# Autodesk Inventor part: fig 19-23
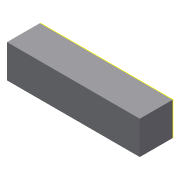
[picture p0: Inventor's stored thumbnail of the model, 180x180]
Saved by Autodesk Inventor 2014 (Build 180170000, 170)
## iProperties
Created: 2013-07
Part Number: fig 19-23
Material: Generic
Document SubType Name: Modeling
Designer: CADCIM
Density: 1 g/cm^3
Appearance: Default
Author: CADCIM
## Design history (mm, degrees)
sketch "Sketch1"
  geometry: L1 (-20, 5)-(20, 5); L2 (20, 5)-(20, -5); L3 (20, -5)-(-20, -5); L4 (-20, -5)-(-20, 5); L5 (-20, 5)-(20, -5); L6 (20, 5)-(-20, -5); 1 further point
  constraints: 12 end point, 2 midpoint, 2 parallel, 1 horizontal, 1 perpendicular
  dimensions: "d0" = 40 distance of L2.end L3.end; "d1" = 10 distance of L1.end L2.end
extrude "Extrusion1" new body sketch "Sketch1" distance "d2" = 10; taper "d3" = 0 deg
sketch "Sketch2"
  geometry: L1 (0, 0)-(40, 0) reference; L2 (0, 0)-(0, -10) reference; L3 (40, -10)-(0, -10) reference; L4 (40, 0)-(40, -10) reference; 2 further points
body "Solid1"
